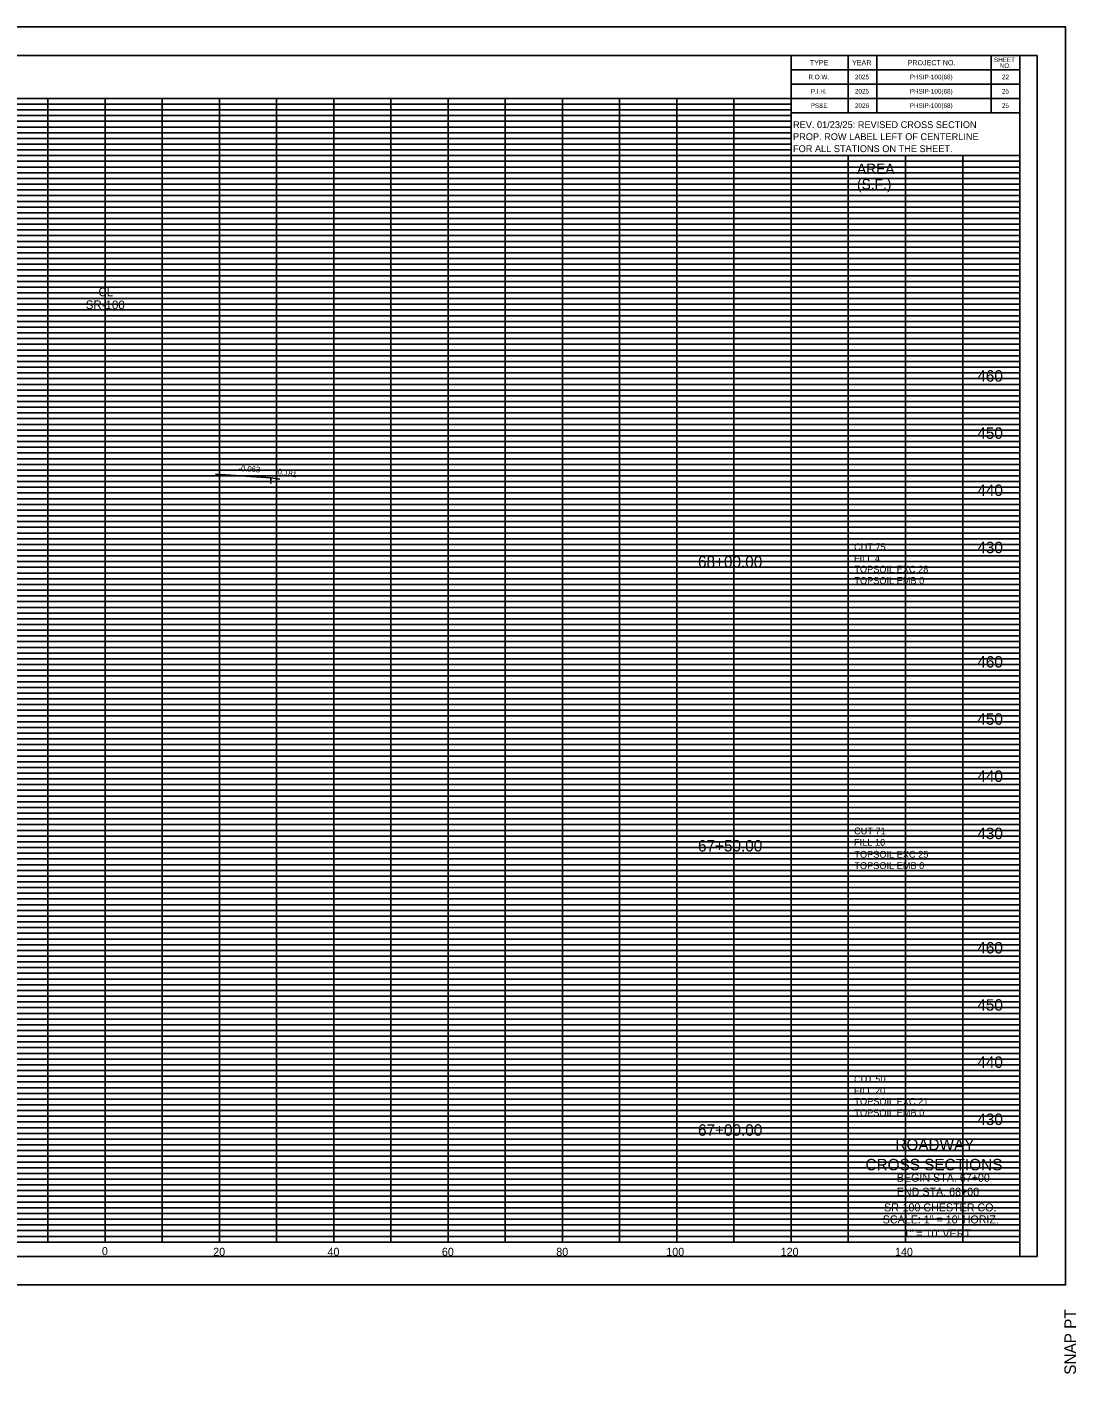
# Model space of a CAD drawing. Extents: x 37 to 1710, y 707 to 2305.
# Drawn here: x 1526.3 to 1709.8, y 976.9 to 1212.5 of the extents above; entities that cross this region are included whole.
import ezdxf

# ---------------------------------------------------------------- set-up
doc = ezdxf.new("R2010")
doc.units = 0
for name, color, linetype in [('DESIGN - DRAINAGE - Special Ditch Width Text', 7, 'Continuous'), ('DESIGN - SCRATCH - User 1', 7, 'Continuous'), ('DESIGN - SHEET - Corner Text', 7, 'Continuous'), ('DESIGN - SHEET - Light Grid', 7, 'Continuous'), ('DESIGN - SHEET - Linework', 7, 'Continuous'), ('DESIGN - SHEET - Plot Shape', 7, 'Continuous'), ('DESIGN - TITLE SHEET - PROJECT LENGTH - ROW', 7, 'Continuous'), ('DESIGN - TYPICAL - Finished Grade and Subgrade', 7, 'Continuous'), ('DESIGN - TYPICAL - Finished Grade Slopes Text', 7, 'Continuous'), ('DESIGN - TYPICAL - Text', 7, 'Continuous')]:
    doc.layers.add(name, color=color, linetype=linetype)

msp = doc.modelspace()

# ---------------------------------------------------------------- linework, layer by layer
at = {"layer": 'DESIGN - SCRATCH - User 1'}
for p, q in [((1665, 1203.75), (1665, 1203.75)), ((1672.5, 1203.75), (1672.5, 1203.75)), ((1685, 1203.75), (1685, 1203.75)), ((1697.5, 1203.75), (1697.5, 1203.75)), ((1665, 1201.25), (1665, 1201.25)), ((1672.5, 1201.25), (1672.5, 1201.25)), ((1685, 1201.25), (1685, 1201.25)), ((1697.5, 1201.25), (1697.5, 1201.25))]:
    msp.add_line(p, q, dxfattribs=at)
at = {"layer": 'DESIGN - SHEET - Light Grid'}
for p, q in [((1380, 1199), (1660, 1199)), ((1380, 1198), (1660, 1198)), ((1380, 1197), (1660, 1197)), ((1380, 1196), (1660, 1196)), ((1380, 1195), (1660, 1195)), ((1380, 1194), (1660, 1194)), ((1380, 1193), (1660, 1193)), ((1380, 1192), (1660, 1192)), ((1380, 1191), (1660, 1191)), ((1380, 1189), (1700, 1189)), ((1380, 1188), (1700, 1188)), ((1380, 1187), (1700, 1187)), ((1380, 1186), (1700, 1186)), ((1380, 1185), (1700, 1185)), ((1380, 1184), (1700, 1184)), ((1380, 1183), (1700, 1183)), ((1380, 1182), (1700, 1182)), ((1380, 1181), (1700, 1181)), ((1380, 1179), (1700, 1179)), ((1380, 1178), (1700, 1178)), ((1380, 1177), (1700, 1177)), ((1380, 1176), (1700, 1176)), ((1380, 1175), (1700, 1175)), ((1380, 1174), (1700, 1174)), ((1380, 1173), (1700, 1173)), ((1380, 1172), (1700, 1172)), ((1380, 1171), (1700, 1171)), ((1380, 1169), (1700, 1169)), ((1380, 1168), (1700, 1168)), ((1380, 1167), (1700, 1167)), ((1380, 1166), (1700, 1166)), ((1380, 1165), (1700, 1165)), ((1380, 1164), (1700, 1164)), ((1380, 1163), (1700, 1163)), ((1380, 1162), (1700, 1162)), ((1380, 1161), (1700, 1161)), ((1380, 1159), (1700, 1159)), ((1380, 1158), (1700, 1158)), ((1380, 1157), (1700, 1157)), ((1380, 1156), (1700, 1156)), ((1380, 1155), (1700, 1155)), ((1380, 1154), (1700, 1154)), ((1380, 1153), (1700, 1153)), ((1380, 1152), (1700, 1152)), ((1380, 1151), (1700, 1151)), ((1380, 1149), (1700, 1149)), ((1380, 1148), (1700, 1148)), ((1380, 1147), (1700, 1147)), ((1380, 1146), (1700, 1146)), ((1380, 1145), (1700, 1145)), ((1380, 1144), (1700, 1144)), ((1380, 1143), (1700, 1143)), ((1380, 1142), (1700, 1142)), ((1380, 1141), (1700, 1141)), ((1380, 1139), (1700, 1139)), ((1380, 1138), (1700, 1138)), ((1380, 1137), (1700, 1137)), ((1380, 1136), (1700, 1136)), ((1380, 1135), (1700, 1135)), ((1380, 1134), (1700, 1134)), ((1380, 1133), (1700, 1133)), ((1380, 1132), (1700, 1132)), ((1380, 1131), (1700, 1131)), ((1380, 1129), (1700, 1129)), ((1380, 1128), (1700, 1128)), ((1380, 1127), (1700, 1127)), ((1380, 1126), (1700, 1126)), ((1380, 1125), (1700, 1125)), ((1380, 1124), (1700, 1124)), ((1380, 1123), (1700, 1123)), ((1380, 1122), (1700, 1122)), ((1380, 1121), (1700, 1121)), ((1380, 1119), (1700, 1119)), ((1380, 1118), (1700, 1118)), ((1380, 1117), (1700, 1117)), ((1380, 1116), (1700, 1116)), ((1380, 1115), (1700, 1115)), ((1380, 1114), (1700, 1114)), ((1380, 1113), (1700, 1113)), ((1380, 1112), (1700, 1112)), ((1380, 1111), (1700, 1111)), ((1380, 1109), (1700, 1109)), ((1380, 1108), (1700, 1108)), ((1380, 1107), (1700, 1107)), ((1380, 1106), (1700, 1106)), ((1380, 1105), (1700, 1105)), ((1380, 1104), (1700, 1104)), ((1380, 1103), (1700, 1103)), ((1380, 1102), (1700, 1102)), ((1380, 1101), (1700, 1101)), ((1380, 1099), (1700, 1099)), ((1380, 1098), (1700, 1098)), ((1380, 1097), (1700, 1097)), ((1380, 1096), (1700, 1096)), ((1380, 1095), (1700, 1095)), ((1380, 1094), (1700, 1094)), ((1380, 1093), (1700, 1093)), ((1380, 1092), (1700, 1092)), ((1380, 1091), (1700, 1091)), ((1380, 1089), (1700, 1089)), ((1380, 1088), (1700, 1088)), ((1380, 1087), (1700, 1087)), ((1380, 1086), (1700, 1086)), ((1380, 1085), (1700, 1085)), ((1380, 1084), (1700, 1084)), ((1380, 1083), (1700, 1083)), ((1380, 1082), (1700, 1082)), ((1380, 1081), (1700, 1081)), ((1380, 1079), (1700, 1079)), ((1380, 1078), (1700, 1078)), ((1380, 1077), (1700, 1077)), ((1380, 1076), (1700, 1076)), ((1380, 1075), (1700, 1075)), ((1380, 1074), (1700, 1074)), ((1380, 1073), (1700, 1073)), ((1380, 1072), (1700, 1072)), ((1380, 1071), (1700, 1071)), ((1380, 1069), (1700, 1069)), ((1380, 1068), (1700, 1068)), ((1380, 1067), (1700, 1067)), ((1380, 1066), (1700, 1066)), ((1380, 1065), (1700, 1065)), ((1380, 1064), (1700, 1064)), ((1380, 1063), (1700, 1063)), ((1380, 1062), (1700, 1062)), ((1380, 1061), (1700, 1061)), ((1380, 1059), (1700, 1059)), ((1380, 1058), (1700, 1058)), ((1380, 1057), (1700, 1057)), ((1380, 1056), (1700, 1056)), ((1380, 1055), (1700, 1055)), ((1380, 1054), (1700, 1054)), ((1380, 1053), (1700, 1053)), ((1380, 1052), (1700, 1052)), ((1380, 1051), (1700, 1051)), ((1380, 1049), (1700, 1049)), ((1380, 1048), (1700, 1048)), ((1380, 1047), (1700, 1047)), ((1380, 1046), (1700, 1046)), ((1380, 1045), (1700, 1045)), ((1380, 1044), (1700, 1044)), ((1380, 1043), (1700, 1043)), ((1380, 1042), (1700, 1042)), ((1380, 1041), (1700, 1041)), ((1380, 1039), (1700, 1039)), ((1380, 1038), (1700, 1038)), ((1380, 1037), (1700, 1037)), ((1380, 1036), (1700, 1036)), ((1380, 1035), (1700, 1035)), ((1380, 1034), (1700, 1034)), ((1380, 1033), (1700, 1033)), ((1380, 1032), (1700, 1032)), ((1380, 1031), (1700, 1031)), ((1380, 1029), (1700, 1029)), ((1380, 1028), (1700, 1028)), ((1380, 1027), (1700, 1027)), ((1380, 1026), (1700, 1026)), ((1380, 1025), (1700, 1025)), ((1380, 1024), (1700, 1024)), ((1380, 1023), (1700, 1023)), ((1380, 1022), (1700, 1022)), ((1380, 1021), (1700, 1021)), ((1380, 1019), (1700, 1019)), ((1380, 1018), (1700, 1018)), ((1380, 1017), (1700, 1017)), ((1380, 1016), (1700, 1016)), ((1380, 1015), (1700, 1015)), ((1380, 1014), (1700, 1014)), ((1380, 1013), (1700, 1013)), ((1380, 1012), (1700, 1012)), ((1380, 1011), (1700, 1011)), ((1380, 1009), (1700, 1009)), ((1380, 1008), (1700, 1008)), ((1380, 1007), (1700, 1007)), ((1380, 1006), (1700, 1006)), ((1380, 1005), (1700, 1005)), ((1380, 1004), (1700, 1004)), ((1380, 1003), (1700, 1003)), ((1380, 1002), (1700, 1002)), ((1380, 1001), (1700, 1001))]:
    msp.add_line(p, q, dxfattribs=at)
at = {"layer": 'DESIGN - SHEET - Linework'}
for p, q in [((1700, 1207.5), (1660, 1207.5)), ((1660, 1200), (1660, 1207.5)), ((1670, 1197.5), (1670, 1207.5)), ((1675, 1197.5), (1675, 1207.5)), ((1695, 1197.5), (1695, 1207.5)), ((1700, 1200), (1700, 1207.5)), ((1700, 1205), (1660, 1205)), ((1700, 1202.5), (1660, 1202.5)), ((1380, 1200), (1700, 1200)), ((1530, 1000), (1530, 1200)), ((1540, 1000), (1540, 1200)), ((1550, 1000), (1550, 1200)), ((1560, 1000), (1560, 1200)), ((1570, 1000), (1570, 1200)), ((1580, 1000), (1580, 1200)), ((1590, 1000), (1590, 1200)), ((1600, 1000), (1600, 1200)), ((1610, 1000), (1610, 1200)), ((1620, 1000), (1620, 1200)), ((1630, 1000), (1630, 1200)), ((1640, 1000), (1640, 1200)), ((1650, 1000), (1650, 1200)), ((1660, 1000), (1660, 1200)), ((1700, 1197.5), (1660, 1197.5)), ((1380, 1190), (1700, 1190)), ((1670, 1000), (1670, 1190)), ((1680, 1000), (1680, 1190)), ((1690, 1000), (1690, 1190)), ((1380, 1180), (1700, 1180)), ((1380, 1170), (1700, 1170)), ((1380, 1160), (1700, 1160)), ((1380, 1150), (1700, 1150)), ((1380, 1140), (1700, 1140)), ((1380, 1130), (1700, 1130)), ((1380, 1120), (1700, 1120)), ((1380, 1110), (1700, 1110)), ((1380, 1100), (1700, 1100)), ((1380, 1090), (1700, 1090)), ((1380, 1080), (1700, 1080)), ((1380, 1070), (1700, 1070)), ((1380, 1060), (1700, 1060)), ((1380, 1050), (1700, 1050)), ((1380, 1040), (1700, 1040)), ((1380, 1030), (1700, 1030)), ((1380, 1020), (1700, 1020)), ((1380, 1010), (1700, 1010)), ((1380, 1000), (1700, 1000))]:
    msp.add_line(p, q, dxfattribs=at)
for points in [[(1368, 1212.5), (1708, 1212.5), (1708, 992.5), (1368, 992.5)], [(1380, 1207.5), (1700, 1207.5), (1700, 997.5), (1380, 997.5)]]:
    msp.add_lwpolyline(points, close=True, dxfattribs=at)
at = {"layer": 'DESIGN - SHEET - Plot Shape'}
msp.add_lwpolyline([(1373, 1207.5), (1703, 1207.5), (1703, 997.5), (1373, 997.5)], close=True, dxfattribs=at)
at = {"layer": 'DESIGN - TYPICAL - Finished Grade and Subgrade'}
for p, q in [((1559.34, 1134.28), (1569.02, 1133.67)), ((1569.02, 1133.67), (1570.56, 1133.39)), ((1569.02, 1133.67), (1569.02, 1132.67))]:
    msp.add_line(p, q, dxfattribs=at)

# ---------------------------------------------------------------- texts
at = {"layer": 'DESIGN - DRAINAGE - Special Ditch Width Text'}
for s, p in [('CL', (1538.85, 1165.42)), ('SR-100', (1536.64, 1163.18))]:
    msp.add_text(s, height=1.5, rotation=359.6675, dxfattribs=at).set_placement(p)
at = {"layer": 'DESIGN - SHEET - Corner Text'}
for s, height, p in [('R.O.W.', 0.8, (1663.02, 1203.35)), ('2025', 0.8, (1671.16, 1203.35)), ('PHSIP-100(68)', 0.8, (1680.75, 1203.35)), ('22', 0.8, (1696.87, 1203.35)), ('P.I.H.', 0.8, (1663.45, 1200.85)), ('2025', 0.8, (1671.16, 1200.85)), ('PHSIP-100(68)', 0.8, (1680.75, 1200.85)), ('25', 0.8, (1696.86, 1200.85)), ('PS&E', 0.8, (1663.42, 1198.35)), ('2026', 0.8, (1671.16, 1198.35)), ('PHSIP-100(68)', 0.8, (1680.75, 1198.35)), ('25', 0.8, (1696.86, 1198.35)), ('ROADWAY ', 2, (1678.23, 1016.05)), ('CROSS SECTIONS', 2, (1673.01, 1012.55)), ('BEGIN STA. 67+00', 1.4, (1678.47, 1010.55)), ('END STA. 68+00', 1.4, (1678.47, 1008.1)), ('SR-100 CHESTER CO.', 1.4, (1676.25, 1005.37)), ('SCALE: 1" = 10\' HORIZ.', 1.4, (1676.02, 1003.26)), ('       1" = 10\' VERT.   ', 1.4, (1676.02, 1000.81))]:
    msp.add_text(s, height=height, dxfattribs=at).set_placement(p)
msp.add_text('SNAP PT  ', height=2, rotation=90, dxfattribs=at).set_placement((1709.8, 976.8))
at = {"layer": 'DESIGN - SHEET - Light Grid'}
for s, height, p in [('TYPE', 0.9, (1663.26, 1205.8)), ('YEAR', 0.9, (1670.66, 1205.8)), ('PROJECT NO.', 0.9, (1680.38, 1205.8)), ('SHEET', 0.8, (1695.47, 1206.35)), ('NO.', 0.8, (1696.47, 1205.35))]:
    msp.add_text(s, height=height, dxfattribs=at).set_placement(p)
at = {"layer": 'DESIGN - TITLE SHEET - PROJECT LENGTH - ROW'}
for s, p in [('REV. 01/23/25: REVISED CROSS SECTION ', (1660.33, 1194.81)), ('PROP. ROW LABEL LEFT OF CENTERLINE ', (1660.33, 1192.71)), ('FOR ALL STATIONS ON THE SHEET.', (1660.33, 1190.61))]:
    msp.add_text(s, height=1.2, rotation=0, dxfattribs=at).set_placement(p)
at = {"layer": 'DESIGN - TYPICAL - Finished Grade Slopes Text'}
for s, rotation, p in [('-0.063', 356.3792, (1563.32, 1134.83)), ('-0.181', 349.7466, (1569.71, 1134.39))]:
    msp.add_text(s, height=1, rotation=rotation, dxfattribs=at).set_placement(p)
at = {"layer": 'DESIGN - TYPICAL - Text'}
for s, height, p in [('AREA ', 1.8, (1671.52, 1186.79)), ('(S.F.)', 1.8, (1671.52, 1184.09)), ('     460     ', 2, (1688.85, 1150.47)), ('     450     ', 2, (1688.85, 1140.47)), ('     440     ', 2, (1688.85, 1130.47)), ('CUT 75', 1.2, (1671, 1120.97)), ('     430     ', 2, (1688.85, 1120.47)), ('     68+00.00     ', 2, (1640, 1117.97)), ('FILL 4', 1.2, (1671, 1118.97)), ('TOPSOIL EXC 28', 1.2, (1671.06, 1117.07)), ('TOPSOIL EMB 0', 1.2, (1671.06, 1115.08)), ('     460     ', 2, (1688.85, 1100.47)), ('     450     ', 2, (1688.85, 1090.47)), ('     440     ', 2, (1688.85, 1080.47)), ('CUT 71', 1.2, (1671, 1071.3)), ('     430     ', 2, (1688.85, 1070.47)), ('     67+50.00     ', 2, (1640, 1068.3)), ('FILL 10', 1.2, (1671, 1069.3)), ('TOPSOIL EXC 25', 1.2, (1671.06, 1067.21)), ('TOPSOIL EMB 0', 1.2, (1671.06, 1065.23)), ('     460     ', 2, (1688.85, 1050.47)), ('     450     ', 2, (1688.85, 1040.47)), ('     440     ', 2, (1688.85, 1030.47)), ('CUT 50', 1.2, (1671, 1027.88)), ('TOPSOIL EXC 21', 1.2, (1671.06, 1024)), ('FILL 20', 1.2, (1671, 1025.88)), ('TOPSOIL EMB 0', 1.2, (1671.06, 1022.02)), ('     430     ', 2, (1688.85, 1020.47)), ('     67+00.00     ', 2, (1640, 1018.6)), ('     0     ', 1.4, (1536.86, 997.72)), ('     0     ', 1.4, (1536.86, 997.72)), ('     20     ', 1.4, (1556.32, 997.6)), ('     40     ', 1.4, (1576.32, 997.6)), ('     60     ', 1.4, (1596.32, 997.6)), ('     80     ', 1.4, (1616.32, 997.6)), ('     100     ', 1.4, (1635.57, 997.6)), ('     120     ', 1.4, (1655.57, 997.6)), ('     140     ', 1.4, (1675.57, 997.6))]:
    msp.add_text(s, height=height, dxfattribs=at).set_placement(p)

doc.saveas('drawing.dxf')
